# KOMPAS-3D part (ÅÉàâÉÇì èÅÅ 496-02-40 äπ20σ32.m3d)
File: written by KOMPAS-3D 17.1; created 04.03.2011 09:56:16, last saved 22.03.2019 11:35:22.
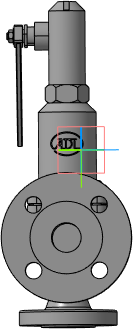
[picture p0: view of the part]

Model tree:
1. Плоскость XY
2. Плоскость ZX
3. Плоскость ZY
4. Ось X
5. Ось Y
6. Ось Z
7. Начало координат
8. Операция без истории:2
